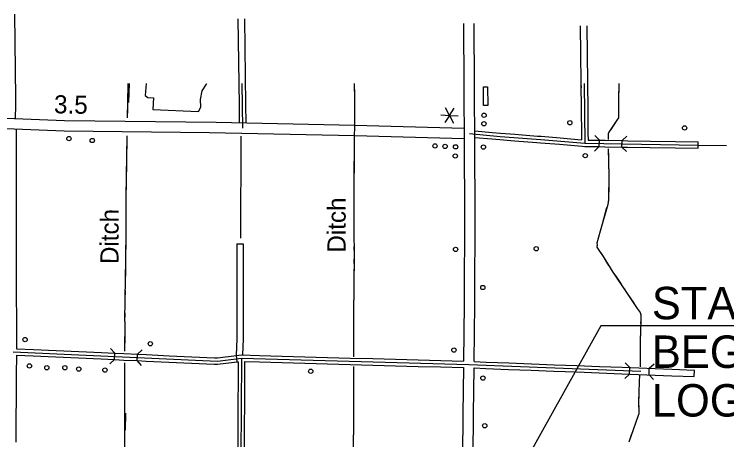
# Model space of a CAD drawing. Extents: x -4306 to 3843, y 131 to 8341.
# Drawn here: x -274 to 2383, y 6723 to 8312 of the extents above; entities that cross this region are included whole.
import ezdxf

# ---------------------------------------------------------------- set-up
doc = ezdxf.new("R2010")
doc.units = 0
for name, color, linetype in [('10', 7, 'Continuous'), ('21', 7, 'Continuous'), ('32', 7, 'Continuous'), ('38', 7, 'Continuous'), ('45', 7, 'Continuous'), ('50', 7, 'Continuous'), ('52', 7, 'Continuous'), ('55', 7, 'Continuous'), ('56', 7, 'Continuous'), ('57', 7, 'Continuous'), ('61', 7, 'Continuous')]:
    doc.layers.add(name, color=color, linetype=linetype)

msp = doc.modelspace()

# ---------------------------------------------------------------- linework, layer by layer
at = {"layer": '10'}
for p, q in [((1401.1, 8278), (1404.4, 7580.5)), ((1444.5, 7580.5), (1441.1, 8277.1)), ((-455.6, 7929.7), (-87, 7915.2)), ((-88, 7875.2), (-457.2, 7889.8)), ((-87, 7915.2), (479.6, 7909.2)), ((454.6, 7869.8), (-88, 7875.2)), ((1403, 7887.1), (1403.2, 7847)), ((1404.4, 7580.5), (1403.2, 7229.5)), ((1443.2, 7229.2), (1444.5, 7580.5)), ((1403.2, 7229.5), (1400.8, 7016.8)), ((1440.8, 7015.4), (1443.2, 7229.2)), ((1400.6, 6992.8), (1398.6, 6820.3)), ((1438.6, 6819.9), (1440.6, 6991.4)), ((1398.6, 6820.3), (1393.1, 6160.5)), ((1433.1, 6159.1), (1438.6, 6819.9))]:
    msp.add_line(p, q, dxfattribs=at)
for points in [[(479.6, 7909.2), (995.2, 7898.2), (1403, 7887.1)], [(1403.2, 7847), (994.2, 7858.2), (454.6, 7869.8)]]:
    msp.add_lwpolyline(points, dxfattribs=at)
at = {"layer": '21'}
msp.add_lwpolyline([(218.4, 8053), (214.3, 8008.3), (224.8, 8001), (245.1, 8000), (242.9, 7956.8), (413.3, 7948.5), (422.3, 7965.6), (420.9, 7994.2), (426.6, 8026.4), (442.7, 8051.4), (443.6, 8053)], dxfattribs=at)
at = {"layer": '32'}
for p, q in [((-272.5, 8312.2), (-269.1, 7999.5)), ((560, 8295.2), (564.2, 7973.2)), ((584, 8294.7), (588.2, 7973.6)), ((1836.7, 8269), (1840.2, 7952.3)), ((1860.7, 8268.5), (1864.2, 7952.6)), ((575.1, 8053), (577.3, 7887.1)), ((1839.1, 8053), (1839.3, 8036.8)), ((1851.1, 8053), (1853.6, 7830.8)), ((1863.1, 8053), (1863.3, 8037)), ((-269.1, 7999.5), (-268.8, 7972.1)), ((-268.8, 7972.1), (-270.2, 7922.4)), ((564.2, 7973.2), (565, 7907.4)), ((588.2, 7973.6), (589, 7906.9)), ((1840.2, 7952.3), (1841.2, 7867.8)), ((1864.2, 7952.6), (1865.2, 7868.1)), ((-267.2, 7882.2), (-267.1, 7851.4)), ((1423.4, 7866.5), (1537.6, 7856)), ((1443, 7876.8), (1508.6, 7870.7)), ((1508.6, 7870.7), (1538.6, 7868)), ((1538.6, 7868), (1592.7, 7863.9)), ((1592.7, 7863.9), (1676.9, 7857.4)), ((1841.2, 7867.8), (1841.4, 7843.8)), ((1865.2, 7868.1), (1865.4, 7842.6)), ((-267.1, 7851.4), (-267, 7766.9)), ((1443.2, 7852.6), (1506.5, 7846.8)), ((1506.5, 7846.8), (1536.6, 7844.1)), ((1536.6, 7844.1), (1590.8, 7839.9)), ((1537.6, 7856), (1689.2, 7844.5)), ((1590.8, 7839.9), (1675.1, 7833.5)), ((1676.9, 7857.4), (1690.2, 7856.4)), ((1689.2, 7844.5), (1853.6, 7830.8)), ((1690.2, 7856.4), (1761.2, 7850.5)), ((1761.2, 7850.5), (1841.4, 7843.8)), ((1865.4, 7842.6), (1907.7, 7841.9)), ((1907.3, 7817.9), (1907.7, 7841.9)), ((1907.7, 7841.9), (1929, 7841.5)), ((1929, 7841.5), (1992.2, 7840.5)), ((1991.8, 7816.5), (1992.2, 7840.5)), ((1992.2, 7840.5), (2013.5, 7840.1)), ((2013.5, 7840.1), (2098, 7838.7)), ((2098, 7838.7), (2191.6, 7837.4)), ((2191.6, 7837.4), (2276.1, 7836)), ((1675.1, 7833.5), (1688.3, 7832.5)), ((1688.3, 7832.5), (1759.2, 7826.6)), ((1759.2, 7826.6), (1843.4, 7819.6)), ((1843.4, 7819.6), (1853, 7818.8)), ((1853, 7818.8), (1907.3, 7817.9)), ((1853.6, 7830.8), (2275.9, 7823.8)), ((1907.3, 7817.9), (1928.6, 7817.5)), ((1928.6, 7817.5), (1991.8, 7816.5)), ((1991.8, 7816.5), (2013.1, 7816.1)), ((2013.1, 7816.1), (2097.6, 7814.7)), ((2097.6, 7814.7), (2191.2, 7813.4)), ((2191.2, 7813.4), (2275.7, 7812)), ((2275.7, 7812), (2276.1, 7836)), ((2275.7, 7812), (2275.7, 7812)), ((2276.1, 7836), (2276.1, 7836)), ((2276.4, 7823.8), (2381.1, 7822)), ((-267, 7766.9), (-266.9, 7682.4)), ((-266.9, 7682.4), (-266.7, 7597.9)), ((-266.7, 7597.9), (-266.6, 7513.4)), ((-266.6, 7513.4), (-266.4, 7428.9)), ((-266.4, 7428.9), (-266.3, 7344.4)), ((-266.3, 7344.4), (-266.1, 7259.9)), ((-266.1, 7259.9), (-266, 7175.4)), ((-266, 7175.4), (-265.9, 7091)), ((-265.9, 7091), (-265.8, 7063.5)), ((-277.8, 7052), (484, 7017.2)), ((-265.8, 7063.5), (-202.3, 7060.6)), ((-202.3, 7060.6), (-117.9, 7056.7)), ((-117.9, 7056.7), (-33.5, 7052.9)), ((-33.5, 7052.9), (50.9, 7049)), ((50.9, 7049), (101.5, 7046.7)), ((100.4, 7022.7), (101.5, 7046.7)), ((101.5, 7046.7), (135.3, 7045.2)), ((135.3, 7045.2), (185.9, 7042.8)), ((184.9, 7018.9), (186, 7042.8)), ((186, 7042.8), (219.7, 7041.3)), ((219.7, 7041.3), (304.1, 7037.4)), ((554.8, 7037.9), (572.6, 7040.1)), ((572.6, 7040.1), (641, 7038.2)), ((-265.9, 7039.5), (-266.4, 6967.4)), ((-265.9, 7039.5), (-203.4, 7036.6)), ((-203.4, 7036.6), (-119, 7032.7)), ((-119, 7032.7), (-34.6, 7028.9)), ((-34.6, 7028.9), (49.8, 7025)), ((49.8, 7025), (100.4, 7022.7)), ((100.4, 7022.7), (134.2, 7021.2)), ((134.2, 7021.2), (184.9, 7018.9)), ((184.9, 7018.9), (218.6, 7017.3)), ((218.6, 7017.3), (303, 7013.5)), ((303, 7013.5), (387.4, 7009.6)), ((304.1, 7037.4), (388.5, 7033.6)), ((388.5, 7033.6), (472.9, 7029.7)), ((472.9, 7029.7), (483.5, 7029.2)), ((483.5, 7029.2), (554.8, 7037.9)), ((484, 7017.2), (573.1, 7028.1)), ((484.4, 7005.2), (557.7, 7014.1)), ((557.7, 7014.1), (554.8, 7037.9)), ((557.7, 7014.1), (561.1, 7014.5)), ((561.1, 7014.5), (560.7, 6943.7)), ((573.1, 7028.1), (569.1, 6177.8)), ((573.1, 7028.1), (1420.9, 7004.2)), ((585.1, 7015.7), (584.7, 6943.5)), ((585.1, 7015.7), (640.3, 7014.2)), ((640.3, 7014.2), (724.7, 7011.8)), ((641, 7038.2), (725.4, 7035.8)), ((725.4, 7035.8), (809.9, 7033.4)), ((809.9, 7033.4), (894.3, 7031)), ((894.3, 7031), (978.8, 7028.7)), ((978.8, 7028.7), (1063.2, 7026.3)), ((1063.2, 7026.3), (1147.7, 7023.9)), ((1147.7, 7023.9), (1232.1, 7021.5)), ((1232.1, 7021.5), (1316.6, 7019.1)), ((1316.6, 7019.1), (1400.8, 7016.8)), ((1440.8, 7015.4), (1485.6, 7013.7)), ((1485.6, 7013.7), (1570, 7010.4)), ((387.4, 7009.6), (471.8, 7005.8)), ((471.8, 7005.8), (484.4, 7005.2)), ((724.7, 7011.8), (809.2, 7009.4)), ((809.2, 7009.4), (893.6, 7007.1)), ((893.6, 7007.1), (978.1, 7004.7)), ((978.1, 7004.7), (1062.6, 7002.3)), ((1062.6, 7002.3), (1147, 6999.9)), ((1147, 6999.9), (1231.5, 6997.5)), ((1231.5, 6997.5), (1315.9, 6995.2)), ((1315.9, 6995.2), (1400.6, 6992.8)), ((1420.9, 7004.2), (2062.4, 6979.2)), ((1440.6, 6991.4), (1484.7, 6989.7)), ((1484.7, 6989.7), (1569.1, 6986.4)), ((1570, 7010.4), (1654.5, 7007.1)), ((1654.5, 7007.1), (1738.9, 7003.8)), ((1738.9, 7003.8), (1823.3, 7000.5)), ((1823.3, 7000.5), (1907.7, 6997.3)), ((1907.7, 6997.3), (1992.2, 6994)), ((1992.2, 6994), (2178.2, 6986.7)), ((2019.8, 6968.9), (2020.8, 6992.9)), ((2092.9, 6966), (2093.8, 6990)), ((2178.2, 6986.7), (2262.7, 6983.4)), ((-266.4, 6967.4), (-266.9, 6883)), ((1569.1, 6986.4), (1653.5, 6983.1)), ((1653.5, 6983.1), (1738, 6979.8)), ((1738, 6979.8), (1822.4, 6976.6)), ((1822.4, 6976.6), (1906.8, 6973.3)), ((1906.8, 6973.3), (1991.2, 6970)), ((1991.2, 6970), (2177.3, 6962.7)), ((2177.3, 6962.7), (2261.7, 6959.4)), ((2261.7, 6959.4), (2262.7, 6983.4)), ((560.7, 6943.7), (560.3, 6859.2)), ((584.7, 6943.5), (584.3, 6859.1)), ((-266.9, 6883), (-267.5, 6798.5)), ((560.3, 6859.2), (559.9, 6774.7)), ((584.3, 6859.1), (583.9, 6774.6)), ((-267.5, 6798.5), (-268, 6714)), ((559.9, 6774.7), (559.5, 6690.2)), ((583.9, 6774.6), (583.5, 6690.1))]:
    msp.add_line(p, q, dxfattribs=at)
at = {"layer": '38'}
for p, q in [((2020.3, 6980.9), (2020.3, 6980.9)), ((2093.3, 6978), (2093.3, 6978))]:
    msp.add_line(p, q, dxfattribs=at)
for points in [[(1891, 7859.1), (1907.7, 7841.9)], [(1992.2, 7840.5), (2009.5, 7857.2)], [(1907.3, 7817.9), (1890.1, 7801.2)], [(2008.5, 7799.2), (1991.8, 7816.5)], [(85.3, 7064.4), (101.5, 7046.7)], [(185.9, 7042.8), (203.6, 7059)], [(100.4, 7022.7), (82.7, 7006.5)], [(201, 7001.1), (184.8, 7018.9)], [(2020.8, 6992.9), (2004.5, 7010.5)], [(2111.4, 7006.3), (2093.8, 6990)], [(2002.2, 6952.6), (2019.8, 6968.9)], [(2092.9, 6966), (2109.2, 6948.4)]]:
    msp.add_lwpolyline(points, dxfattribs=at)
at = {"layer": '45'}
for p, q in [((556, 7455.4), (555.7, 7370.9)), ((556, 7455.4), (580, 7455.3)), ((580, 7455.3), (579.7, 7370.8)), ((555.7, 7370.9), (555.7, 7357.6)), ((579.7, 7370.8), (579.7, 7357.6)), ((555.7, 7357.6), (555.9, 7295.9)), ((579.7, 7357.6), (579.9, 7296)), ((555.9, 7286.4), (555.8, 7240.9)), ((555.9, 7295.9), (555.9, 7286.4)), ((579.9, 7286.3), (579.8, 7240.9)), ((579.9, 7296), (579.9, 7286.3)), ((555.8, 7240.9), (555.9, 7201.8)), ((579.8, 7240.9), (579.9, 7201.9)), ((555.9, 7201.8), (556, 7178.2)), ((579.9, 7201.9), (580, 7178.1)), ((556, 7178.2), (555.6, 7117.5)), ((580, 7178.1), (579.6, 7117.3)), ((555.5, 7099.7), (553.6, 7037.8)), ((555.6, 7117.5), (555.5, 7099.7)), ((579.5, 7099.2), (577.7, 7040)), ((579.6, 7117.3), (579.5, 7099.2))]:
    msp.add_line(p, q, dxfattribs=at)
at = {"layer": '50'}
for p, q in [((1913.7, 7148.4), (887.6, 5313.5)), ((3572.5, 7148.4), (1913.7, 7148.4))]:
    msp.add_line(p, q, dxfattribs=at)
at = {"layer": '52'}
msp.add_line((570.5, 7476.7), (572.4, 7856.4), dxfattribs=at)
at = {"layer": '55'}
msp.add_line((154.2, 8053), (152.5, 7982.5), dxfattribs=at)
at = {"layer": '56'}
for points in [[(148.8, 7925.6), (150.4, 8047.3), (150.5, 8053)], [(994, 8053), (994.3, 8011.8), (994.3, 7898.3), (994, 7850.2), (992.7, 7679.5), (992.1, 7501.2), (993, 7416.6), (992.4, 7289.5), (991, 7200.5)], [(1979.9, 8053), (1979.9, 8049), (1978.7, 7989.5)], [(1979.9, 8053), (1979.9, 8049), (1978.9, 8000.9)], [(149.5, 7978.4), (150.4, 8041.8)], [(994.1, 8035.8), (994.3, 8011.8), (994.3, 7972.4)], [(1978.7, 7989.5), (1979.2, 7933.6), (1978.8, 7925.1), (1973.1, 7916.2), (1943.4, 7872.3), (1941.1, 7865.8), (1940.9, 7844.8)], [(1978.7, 7989.5), (1979, 7957.8)], [(148.8, 7925.6), (149.3, 7957.3)], [(994.3, 7951.3), (994.3, 7898.3), (994.2, 7887.9)], [(1979.2, 7936.7), (1979.2, 7933.6), (1978.8, 7925.1), (1973.1, 7916.2), (1950, 7882.1)], [(994.1, 7866.8), (994, 7850.2), (993.6, 7803.4)], [(1941.1, 7863.4), (1940.9, 7844.8)], [(138.8, 7164.7), (140.3, 7249.7), (143, 7470.6), (143.8, 7631), (146.4, 7783.1), (147.7, 7857.9)], [(146.9, 7808.9), (147.7, 7857.9)], [(145.4, 7724.4), (146.4, 7783.1), (146.5, 7787.8)], [(1940.8, 7809.8), (1943, 7711.5), (1942.1, 7620.9), (1938.7, 7602.4), (1910.7, 7502.8), (1898.1, 7457.6), (1899.2, 7450.2), (1898.4, 7442.8), (1921.3, 7408.2), (1957.9, 7349.8), (2011.5, 7269.8), (2049.2, 7213.8), (2060.3, 7198.5), (2061.8, 7190.1), (2061.9, 7172.8), (2060.3, 7088.7), (2060.1, 7004.5), (2059.8, 6996)], [(1940.8, 7809.8), (1941.5, 7778.1)], [(993.5, 7782.3), (993, 7719)], [(1942, 7757), (1943, 7711.5), (1942.8, 7693.6)], [(144.5, 7671.6), (145, 7703.3)], [(992.8, 7697.8), (992.7, 7679.5), (992.7, 7666.2)], [(143.9, 7639.9), (144.5, 7671.6)], [(992.7, 7666.2), (992.5, 7634.5)], [(1942.6, 7672.5), (1942.1, 7620.9), (1940, 7609.3)], [(143.4, 7555.5), (143.7, 7618.8)], [(992.5, 7613.4), (992.3, 7550)], [(1934.9, 7588.9), (1917.7, 7527.9)], [(143, 7471), (143.3, 7534.3)], [(992.2, 7528.9), (992.1, 7501.2), (992.5, 7465.5)], [(1912, 7507.5), (1910.7, 7502.8), (1898.1, 7457.6), (1899.2, 7450.2), (1898.8, 7446.2)], [(142, 7386.5), (142.7, 7449.8)], [(992.7, 7444.4), (993, 7416.6), (992.8, 7381)], [(1908.2, 7428), (1921.3, 7408.2), (1942.3, 7374.6)], [(141, 7302), (141.7, 7365.4)], [(992.7, 7359.9), (992.4, 7296.5)], [(1953.5, 7356.7), (1957.9, 7349.8), (1971, 7330.3)], [(1971, 7330.3), (1988.6, 7304)], [(139.8, 7217.5), (140.3, 7249.7), (140.7, 7280.9)], [(2000.4, 7286.4), (2011.5, 7269.8), (2035.7, 7233.8)], [(992.2, 7275.4), (991.2, 7212)], [(991, 7200.5), (991.6, 7124.9), (991.2, 7032.7)], [(991, 7200.5), (991.3, 7168.8)], [(2047.5, 7216.3), (2049.2, 7213.8), (2060.3, 7198.5), (2061.8, 7190.1), (2061.9, 7172.8), (2061.6, 7157.2)], [(138.8, 7164.7), (139.4, 7196.4)], [(138.8, 7164.7), (137.5, 7053.9)], [(138.8, 7164.7), (138.5, 7133)], [(991.4, 7147.7), (991.6, 7124.9), (991.4, 7084.3)], [(2061.2, 7136), (2060.3, 7088.7), (2060.3, 7072.7)], [(138.2, 7111.9), (137.5, 7053.9)], [(991.3, 7063.2), (991.2, 7032.7)], [(2060.2, 7051.6), (2060.1, 7004.5), (2059.8, 6996)], [(137, 7010.5), (136.7, 6978.4), (137.2, 6875.4), (136.8, 6800.3), (136.9, 6727.5), (136.9, 6612.5), (136.7, 6457.1), (136.1, 6359.3), (136, 6263.3), (137.2, 6210)], [(137, 7010.5), (136.7, 6978.8)], [(990.8, 6996.5), (990.7, 6986.2), (991, 6793.8), (990.1, 6688.9), (989.1, 6602.1), (990.1, 6491.2), (989.9, 6377.6), (988.5, 6273.2), (989.3, 6201.9), (988.9, 6184.6)], [(990.8, 6996.5), (990.7, 6986.2), (990.8, 6964.8)], [(2018.5, 6715.3), (2052.2, 6811.3), (2055.6, 6821.5), (2055.7, 6833.3), (2055.3, 6856.5), (2057.5, 6941.1), (2058.4, 6963.3)], [(2057.2, 6930.7), (2057.5, 6941.1), (2058.4, 6963.3)], [(136.8, 6957.7), (137.1, 6894.3)], [(990.8, 6943.7), (990.9, 6880.3)], [(2055.5, 6846.3), (2055.3, 6856.5), (2056.7, 6909.6)], [(137.2, 6873.2), (136.8, 6809.8)], [(990.9, 6859.2), (991, 6795.8)], [(140.7, 6822.4), (140.3, 6759)], [(2036, 6765.1), (2052.2, 6811.3), (2055.6, 6821.5), (2055.6, 6825.2)], [(136.8, 6788.7), (136.9, 6727.5), (136.9, 6725.3)], [(990.8, 6774.7), (990.3, 6711.4)], [(2018.5, 6715.3), (2029, 6745.2)]]:
    msp.add_lwpolyline(points, dxfattribs=at)
at = {"layer": '57'}
msp.add_lwpolyline([(1491.5, 7971.2), (1475.5, 7971.1), (1475.1, 8041.1), (1491.1, 8041.2)], close=True, dxfattribs=at)
for centre in [(1477.9, 7935.1), (1477.1, 7903.1), (1797.6, 7906.9), (2225.6, 7887.6), (-70, 7848), (17.1, 7840.8), (1294.8, 7820.7), (1332.4, 7818.8), (1371.8, 7817.1), (1475.2, 7816.4), (1370.6, 7782.9), (1855.2, 7784.2), (1371.6, 7434), (1672.1, 7436.6), (1473.2, 7291.9), (-233.4, 7097.3), (233.5, 7081.9), (1365.4, 7058.3), (-217.5, 6999.3), (-152.4, 6992.5), (-85.2, 6992.1), (-33.4, 6987.3), (64.3, 6983.8), (831.6, 6979.2), (1473.4, 6953.6), (1480.5, 6775.9)]:
    msp.add_circle(centre, 8, dxfattribs=at)
at = {"layer": '61'}
for p, q in [((1348.8, 7934.5), (1334.2, 7963)), ((1348.8, 7934.5), (1366.1, 7961.4)), ((1316.8, 7936.1), (1348.8, 7934.5)), ((1348.8, 7934.5), (1331.4, 7907.6)), ((1348.8, 7934.5), (1380.7, 7932.9)), ((1348.8, 7934.5), (1363.4, 7906))]:
    msp.add_line(p, q, dxfattribs=at)

# ---------------------------------------------------------------- texts
at = {"layer": '50'}
for s, p in [('STA. 304+46.00', (2103.5, 7173.3)), ('BEGIN SITE 3', (2103.5, 6991.7)), ('LOG MILE 2.45', (2103.5, 6810.1))]:
    msp.add_text(s, height=121.064, dxfattribs=at).set_placement(p)
at = {"layer": '56'}
for p in [(961.3, 7422), (114.8, 7379.3)]:
    msp.add_text('Ditch', height=67.59, rotation=89.818, dxfattribs=at).set_placement(p)
at = {"layer": '61'}
msp.add_text('3.5', height=67.59, rotation=358.8534, dxfattribs=at).set_placement((-126.2, 7942.5))

doc.saveas('drawing.dxf')
